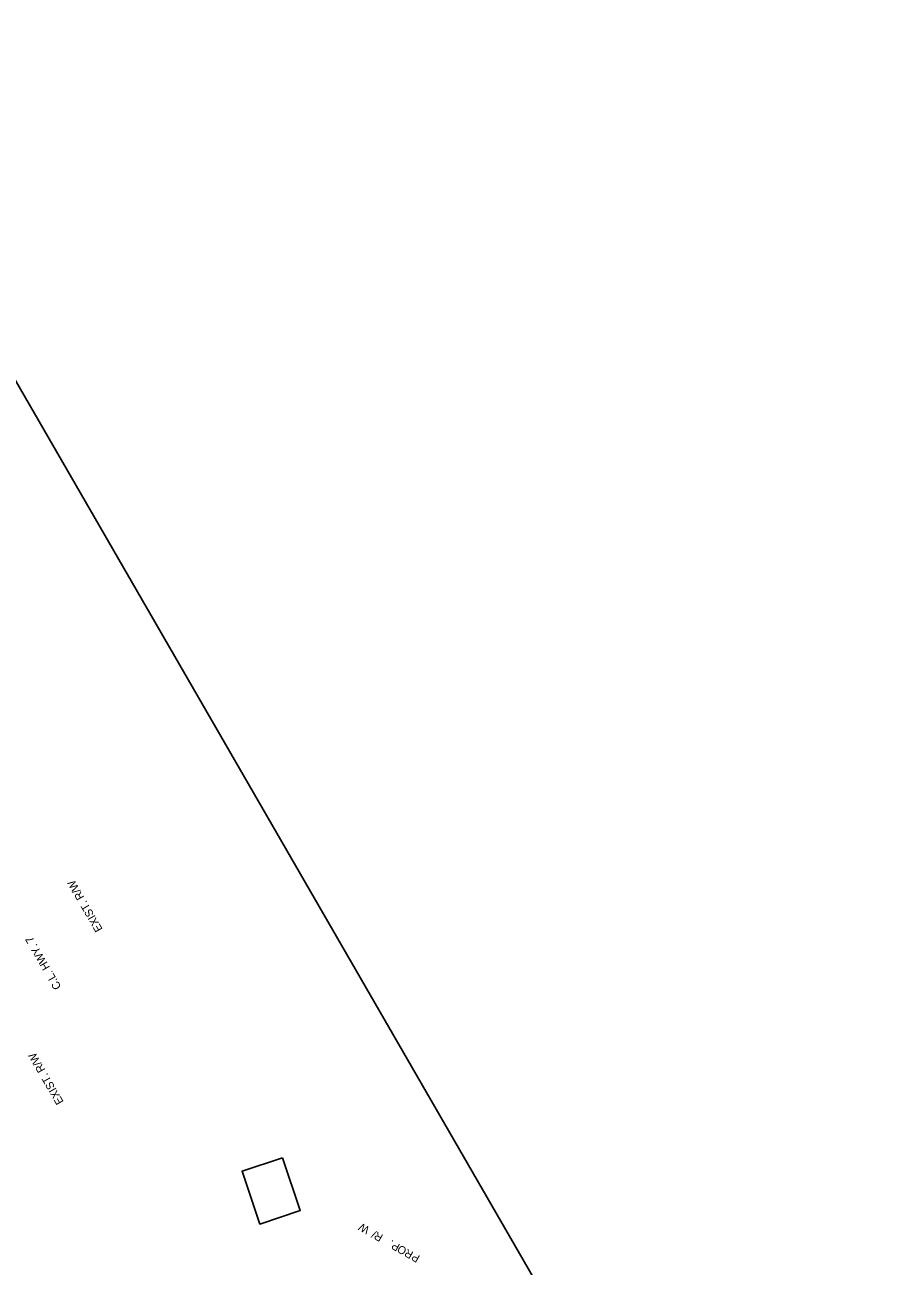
# Model space of a CAD drawing. Extents: x 956270 to 957915, y 1920520 to 1922423.
# Drawn here: x 957279 to 957915, y 1921493 to 1922423 of the extents above; entities that cross this region are included whole.
import ezdxf

# ---------------------------------------------------------------- set-up
doc = ezdxf.new("R2010")
doc.units = 0
doc.layers.add('NO PLOT', color=7, linetype='Continuous')
doc.layers.add('R_Draft', color=7, linetype='Continuous')

msp = doc.modelspace()

# ---------------------------------------------------------------- linework, layer by layer
at = {"layer": 'NO PLOT'}
for points in [[(957915.18, 1921041.6), (957117.5, 1922423.23), (956666.17, 1922162.65), (956816.66, 1921901.98), (956875.12, 1921935.73), (957087.62, 1921567.67), (957029.16, 1921533.92), (957172.25, 1921286.08), (957225.74, 1921316.96), (957397.07, 1921020.21), (957343.58, 1920989.33), (957463.85, 1920781.02)], [(957915.18, 1921041.6), (957117.5, 1922423.23), (956666.17, 1922162.65), (956816.66, 1921901.98), (956875.12, 1921935.73), (957087.62, 1921567.67), (957029.16, 1921533.92), (957172.25, 1921286.08), (957225.74, 1921316.96), (957397.07, 1921020.21), (957343.58, 1920989.33), (957463.85, 1920781.02)], [(957915.18, 1921041.6), (957117.5, 1922423.23), (956666.17, 1922162.65), (956816.66, 1921901.98), (956875.12, 1921935.73), (957087.62, 1921567.67), (957029.16, 1921533.92), (957172.25, 1921286.08), (957225.74, 1921316.96), (957397.07, 1921020.21), (957343.58, 1920989.33), (957463.85, 1920781.02)], [(957915.18, 1921041.6), (957117.5, 1922423.23), (956666.17, 1922162.65), (956816.66, 1921901.98), (956875.12, 1921935.73), (957087.62, 1921567.67), (957029.16, 1921533.92), (957172.25, 1921286.08), (957225.74, 1921316.96), (957397.07, 1921020.21), (957343.58, 1920989.33), (957463.85, 1920781.02)], [(957915.18, 1921041.6), (957117.5, 1922423.23), (956666.17, 1922162.65), (956816.66, 1921901.98), (956875.12, 1921935.73), (957087.62, 1921567.67), (957029.16, 1921533.92), (957172.25, 1921286.08), (957225.74, 1921316.96), (957397.07, 1921020.21), (957343.58, 1920989.33), (957463.85, 1920781.02)], [(957915.18, 1921041.6), (957117.5, 1922423.23), (956666.17, 1922162.65), (956816.66, 1921901.98), (956875.12, 1921935.73), (957087.62, 1921567.67), (957029.16, 1921533.92), (957172.25, 1921286.08), (957225.74, 1921316.96), (957397.07, 1921020.21), (957343.58, 1920989.33), (957463.85, 1920781.02)], [(957471.72, 1921573.95), (957485.01, 1921534.44), (957454.76, 1921524.27), (957441.48, 1921563.78)]]:
    msp.add_lwpolyline(points, close=True, dxfattribs=at)

# ---------------------------------------------------------------- texts
at = {"layer": 'R_Draft'}
for s, rotation, p in [('EXIST. R/W', 119.9486, (957337.11, 1921745.3)), ('C.L. HWY. 7', 119.98842, (957306.13, 1921702.01)), ('EXIST. R/W', 119.9486, (957307.86, 1921615.9)), ('W', 150.5183, (957537.57, 1921521.57)), ('/', 150.5183, (957542.67, 1921518.69)), ('R', 150.5183, (957547.6, 1921515.9)), ('P', 150.5183, (957560.31, 1921508.71)), ('.', 150.5183, (957555.38, 1921511.5)), ('O', 150.5183, (957565.41, 1921505.83)), ('R', 150.5183, (957570.35, 1921503.04)), ('P', 150.5183, (957575.28, 1921500.25))]:
    msp.add_text(s, height=6, rotation=rotation, dxfattribs=at).set_placement(p)

doc.saveas('drawing.dxf')
